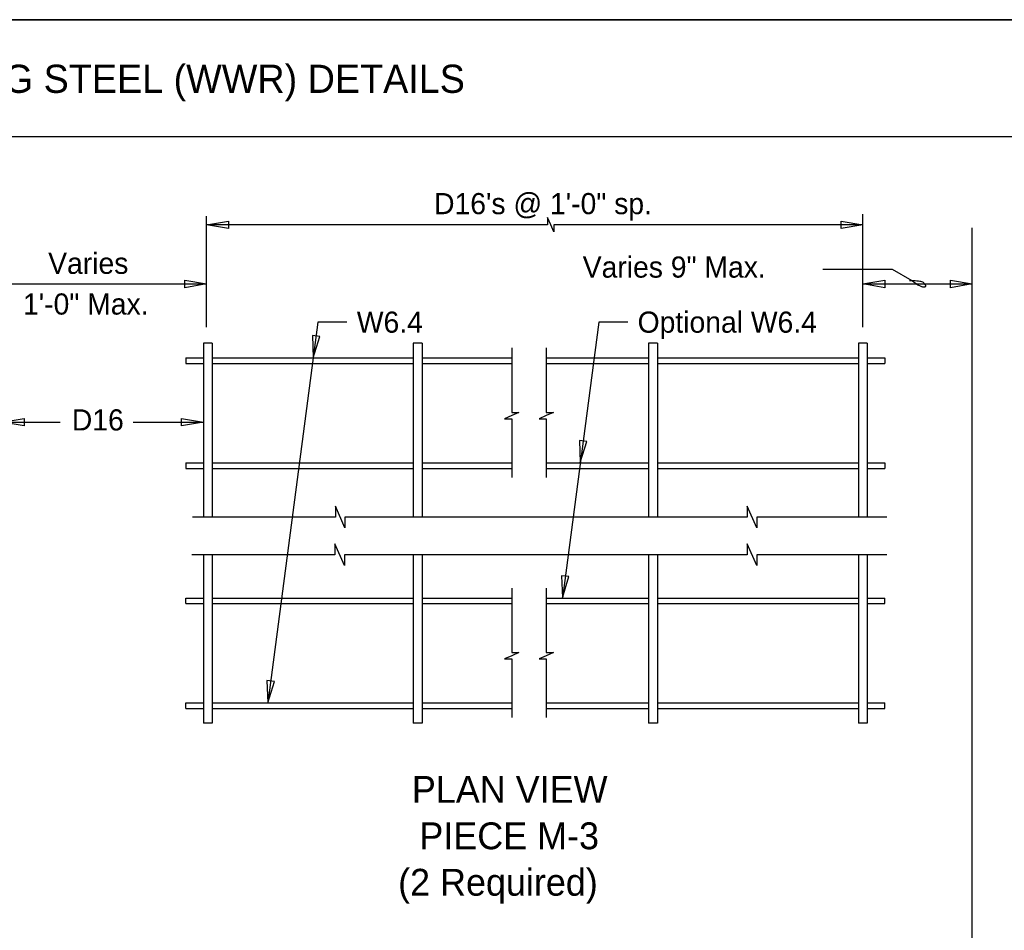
# Model space of a CAD drawing. Extents: x 0 to 20.5, y 0 to 13.
# Drawn here: x 10.078 to 14.769, y 8.632 to 12.973 of the extents above; entities that cross this region are included whole.
import ezdxf

# ---------------------------------------------------------------- set-up
doc = ezdxf.new("R2010")
doc.units = 0
for name, color, linetype in [('ActivePts-ConstElements', 7, 'Continuous'), ('CL_Minor', 7, 'Continuous'), ('Dimension', 7, 'Continuous'), ('Miscellaneous1', 7, 'Continuous'), ('Rebar', 7, 'Continuous'), ('Symbols', 7, 'Continuous'), ('TextStructures', 7, 'Continuous')]:
    doc.layers.add(name, color=color, linetype=linetype)

msp = doc.modelspace()

# ---------------------------------------------------------------- linework, layer by layer
at = {"layer": 'ActivePts-ConstElements'}
msp.add_lwpolyline([(0, 0), (20.5333, 0), (20.5333, 12.9731), (0, 12.9731)], close=True, dxfattribs=at)
at = {"layer": 'CL_Minor'}
msp.add_line((14.6167, 1.1474), (14.6167, 11.9813), dxfattribs=at)
at = {"layer": 'Dimension'}
for p, q in [((0, 12.4165), (20.5333, 12.4165)), ((10.9688, 11.5072), (10.9688, 12.0356)), ((14.0953, 11.5072), (14.0953, 12.0458)), ((9.974, 11.7132), (10.9688, 11.7132)), ((14.0953, 11.7132), (14.6167, 11.7132)), ((9.4949, 11.0541), (10.2715, 11.0541)), ((10.6186, 11.0541), (10.9532, 11.0541))]:
    msp.add_line(p, q, dxfattribs=at)
for points in [[(14.0953, 11.9954), (12.6232, 11.9954), (12.6232, 11.9609), (12.6082, 11.9954), (12.5932, 12.0298), (12.5932, 11.9954), (10.9688, 11.9954)], [(13.9041, 11.783), (14.2355, 11.783), (14.329, 11.7289)], [(11.6372, 11.5313), (11.4994, 11.5313), (11.2603, 9.7169)], [(12.975, 11.5313), (12.8372, 11.5313), (12.6638, 10.2157)], [(12.4223, 11.408), (12.4223, 11.1007), (12.4568, 11.1007), (12.4223, 11.0857), (12.3879, 11.0707), (12.4223, 11.0707), (12.4223, 10.7907)], [(12.587, 11.408), (12.587, 11.1007), (12.6214, 11.1007), (12.587, 11.0857), (12.5525, 11.0707), (12.587, 11.0707), (12.587, 10.7907)], [(12.4223, 10.2632), (12.4223, 9.9559), (12.4568, 9.9559), (12.4223, 9.9409), (12.3879, 9.9259), (12.4223, 9.9259), (12.4223, 9.6459)], [(12.587, 10.2632), (12.587, 9.9559), (12.6214, 9.9559), (12.587, 9.9409), (12.5525, 9.9259), (12.587, 9.9259), (12.587, 9.6459)]]:
    msp.add_lwpolyline(points, dxfattribs=at)
for points in [[(11.0729, 11.9777), (10.9688, 11.9954), (11.0729, 12.013)], [(11.0729, 11.9777), (10.9688, 11.9954), (11.0729, 12.013)], [(13.9912, 12.013), (14.0953, 11.9954), (13.9912, 11.9777)], [(10.8647, 11.7308), (10.9688, 11.7132), (10.8647, 11.6955)], [(14.1994, 11.6955), (14.0953, 11.7132), (14.1994, 11.7308)], [(14.5126, 11.7308), (14.6167, 11.7132), (14.5126, 11.6955)], [(11.4731, 11.4672), (11.477, 11.3617), (11.5081, 11.4626)], [(10.099, 11.0364), (9.9949, 11.0541), (10.099, 11.0717)], [(10.8491, 11.0717), (10.9532, 11.0541), (10.8491, 11.0364)], [(12.7451, 10.9672), (12.749, 10.8617), (12.78, 10.9626)], [(12.6602, 10.3224), (12.6641, 10.2169), (12.6952, 10.3178)], [(11.2564, 9.8224), (11.2603, 9.7169), (11.2914, 9.8178)]]:
    msp.add_lwpolyline(points, close=True, dxfattribs=at)
msp.add_open_spline([(14.329, 11.7289), (14.3677, 11.6997), (14.396, 11.6997), (14.396, 11.7059), (14.3775, 11.7286), (14.3167, 11.7286)], degree=2, dxfattribs=at)
at = {"layer": 'Miscellaneous1'}
msp.add_lwpolyline([(0, 12.9731), (20.5333, 12.9731), (20.5333, 0), (0, 0)], close=True, dxfattribs=at)
at = {"layer": 'Rebar'}
for p, q in [((10.9949, 11.4305), (10.9532, 11.4305)), ((10.9532, 11.4305), (10.9532, 10.6014)), ((10.9949, 11.4305), (10.9949, 10.6014)), ((11.9949, 11.4305), (11.9532, 11.4305)), ((11.9532, 11.4305), (11.9532, 10.6014)), ((11.9949, 11.4305), (11.9949, 10.6014)), ((13.1162, 11.4305), (13.0745, 11.4305)), ((13.0745, 11.4305), (13.0745, 10.6014)), ((13.1162, 11.4305), (13.1162, 10.6014)), ((14.1162, 11.4305), (14.0745, 11.4305)), ((14.0745, 11.4305), (14.0745, 10.6014)), ((14.1162, 11.4305), (14.1162, 10.6014)), ((10.8699, 11.3605), (10.9532, 11.3605)), ((10.8699, 11.3605), (10.8699, 11.3339)), ((10.9949, 11.3605), (11.9532, 11.3605)), ((11.9949, 11.3605), (12.4223, 11.3605)), ((12.587, 11.3605), (13.0745, 11.3605)), ((13.1162, 11.3605), (14.0745, 11.3605)), ((14.1162, 11.3605), (14.1995, 11.3605)), ((14.1995, 11.3605), (14.1995, 11.3339)), ((10.8699, 11.3339), (10.9532, 11.3339)), ((10.9949, 11.3339), (11.9532, 11.3339)), ((11.9949, 11.3339), (12.4223, 11.3339)), ((12.587, 11.3339), (13.0745, 11.3339)), ((13.1162, 11.3339), (14.0745, 11.3339)), ((14.1162, 11.3339), (14.1995, 11.3339)), ((10.8699, 10.8605), (10.9532, 10.8605)), ((10.8699, 10.8605), (10.8699, 10.8339)), ((10.9949, 10.8605), (11.9532, 10.8605)), ((11.9949, 10.8605), (12.4223, 10.8605)), ((12.587, 10.8605), (13.0745, 10.8605)), ((13.1162, 10.8605), (14.0745, 10.8605)), ((14.1162, 10.8605), (14.1995, 10.8605)), ((14.1995, 10.8605), (14.1995, 10.8339)), ((10.8699, 10.8339), (10.9532, 10.8339)), ((10.9949, 10.8339), (11.9532, 10.8339)), ((11.9949, 10.8339), (12.4223, 10.8339)), ((12.587, 10.8339), (13.0745, 10.8339)), ((13.1162, 10.8339), (14.0745, 10.8339)), ((14.1162, 10.8339), (14.1995, 10.8339)), ((10.9532, 10.4224), (10.9532, 9.6191)), ((10.9949, 10.4224), (10.9949, 9.6191)), ((11.9532, 10.4224), (11.9532, 9.6191)), ((11.9949, 10.4224), (11.9949, 9.6191)), ((13.0745, 10.4224), (13.0745, 9.6191)), ((13.1162, 10.4224), (13.1162, 9.6191)), ((14.0745, 10.4224), (14.0745, 9.6191)), ((14.1162, 10.4224), (14.1162, 9.6191)), ((10.8699, 10.2157), (10.9532, 10.2157)), ((10.8699, 10.1891), (10.8699, 10.2157)), ((10.8699, 10.1891), (10.9532, 10.1891)), ((10.9949, 10.2157), (11.9532, 10.2157)), ((10.9949, 10.1891), (11.9532, 10.1891)), ((11.9949, 10.2157), (12.4223, 10.2157)), ((11.9949, 10.1891), (12.4223, 10.1891)), ((12.587, 10.2157), (13.0745, 10.2157)), ((12.587, 10.1891), (13.0745, 10.1891)), ((13.1162, 10.2157), (14.0745, 10.2157)), ((13.1162, 10.1891), (14.0745, 10.1891)), ((14.1162, 10.2157), (14.1995, 10.2157)), ((14.1162, 10.1891), (14.1995, 10.1891)), ((14.1995, 10.1891), (14.1995, 10.2157)), ((10.8699, 9.7157), (10.9532, 9.7157)), ((10.8699, 9.6891), (10.8699, 9.7157)), ((10.9949, 9.7157), (11.9532, 9.7157)), ((11.9949, 9.7157), (12.4223, 9.7157)), ((12.587, 9.7157), (13.0745, 9.7157)), ((13.1162, 9.7157), (14.0745, 9.7157)), ((14.1162, 9.7157), (14.1995, 9.7157)), ((14.1995, 9.6891), (14.1995, 9.7157)), ((10.8699, 9.6891), (10.9532, 9.6891)), ((10.9949, 9.6891), (11.9532, 9.6891)), ((11.9949, 9.6891), (12.4223, 9.6891)), ((12.587, 9.6891), (13.0745, 9.6891)), ((13.1162, 9.6891), (14.0745, 9.6891)), ((14.1162, 9.6891), (14.1995, 9.6891)), ((10.9949, 9.6191), (10.9532, 9.6191)), ((11.9949, 9.6191), (11.9532, 9.6191)), ((13.1162, 9.6191), (13.0745, 9.6191)), ((14.1162, 9.6191), (14.0745, 9.6191))]:
    msp.add_line(p, q, dxfattribs=at)
at = {"layer": 'Symbols'}
for points in [[(12.7116, 10.6014), (11.6272, 10.6014), (11.6272, 10.5498), (11.5822, 10.6531), (11.5822, 10.6014), (10.9013, 10.6014)], [(14.2092, 10.6014), (13.5897, 10.6014), (13.5897, 10.5498), (13.5447, 10.6531), (13.5447, 10.6014), (12.7116, 10.6014)], [(12.7116, 10.4224), (11.6249, 10.4224), (11.6249, 10.3707), (11.5799, 10.4741), (11.5799, 10.4224), (10.899, 10.4224)], [(14.2092, 10.4224), (13.5897, 10.4224), (13.5897, 10.3707), (13.5447, 10.4741), (13.5447, 10.4224), (12.7116, 10.4224)]]:
    msp.add_lwpolyline(points, dxfattribs=at)

# ---------------------------------------------------------------- texts
at = {"layer": 'Dimension'}
for s, p in [('D16\'s @ 1\'-0" sp.', (12.0526, 12.0458)), ('Varies', (10.2139, 11.7613)), ('Varies 9" Max.', (12.7607, 11.7433)), ('1\'-0" Max.', (10.0941, 11.5672)), ('Optional W6.4', (13.0222, 11.4807)), ('W6.4', (11.6844, 11.4807)), ('D16', (10.3268, 11.0147))]:
    msp.add_text(s, height=0.1008, dxfattribs=at).set_placement(p)
at = {"layer": 'TextStructures'}
for s, height, p in [('ALTERNATE REINFORCING STEEL (WWR) DETAILS', 0.1344, (7.7757, 12.6241)), ('PLAN VIEW', 0.128, (11.9467, 9.2396)), ('PIECE M-3', 0.128, (11.9823, 9.0183)), ('(2 Required)', 0.128, (11.8811, 8.7969))]:
    msp.add_text(s, height=height, dxfattribs=at).set_placement(p)

doc.saveas('drawing.dxf')
